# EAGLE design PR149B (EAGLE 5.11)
PID: 626
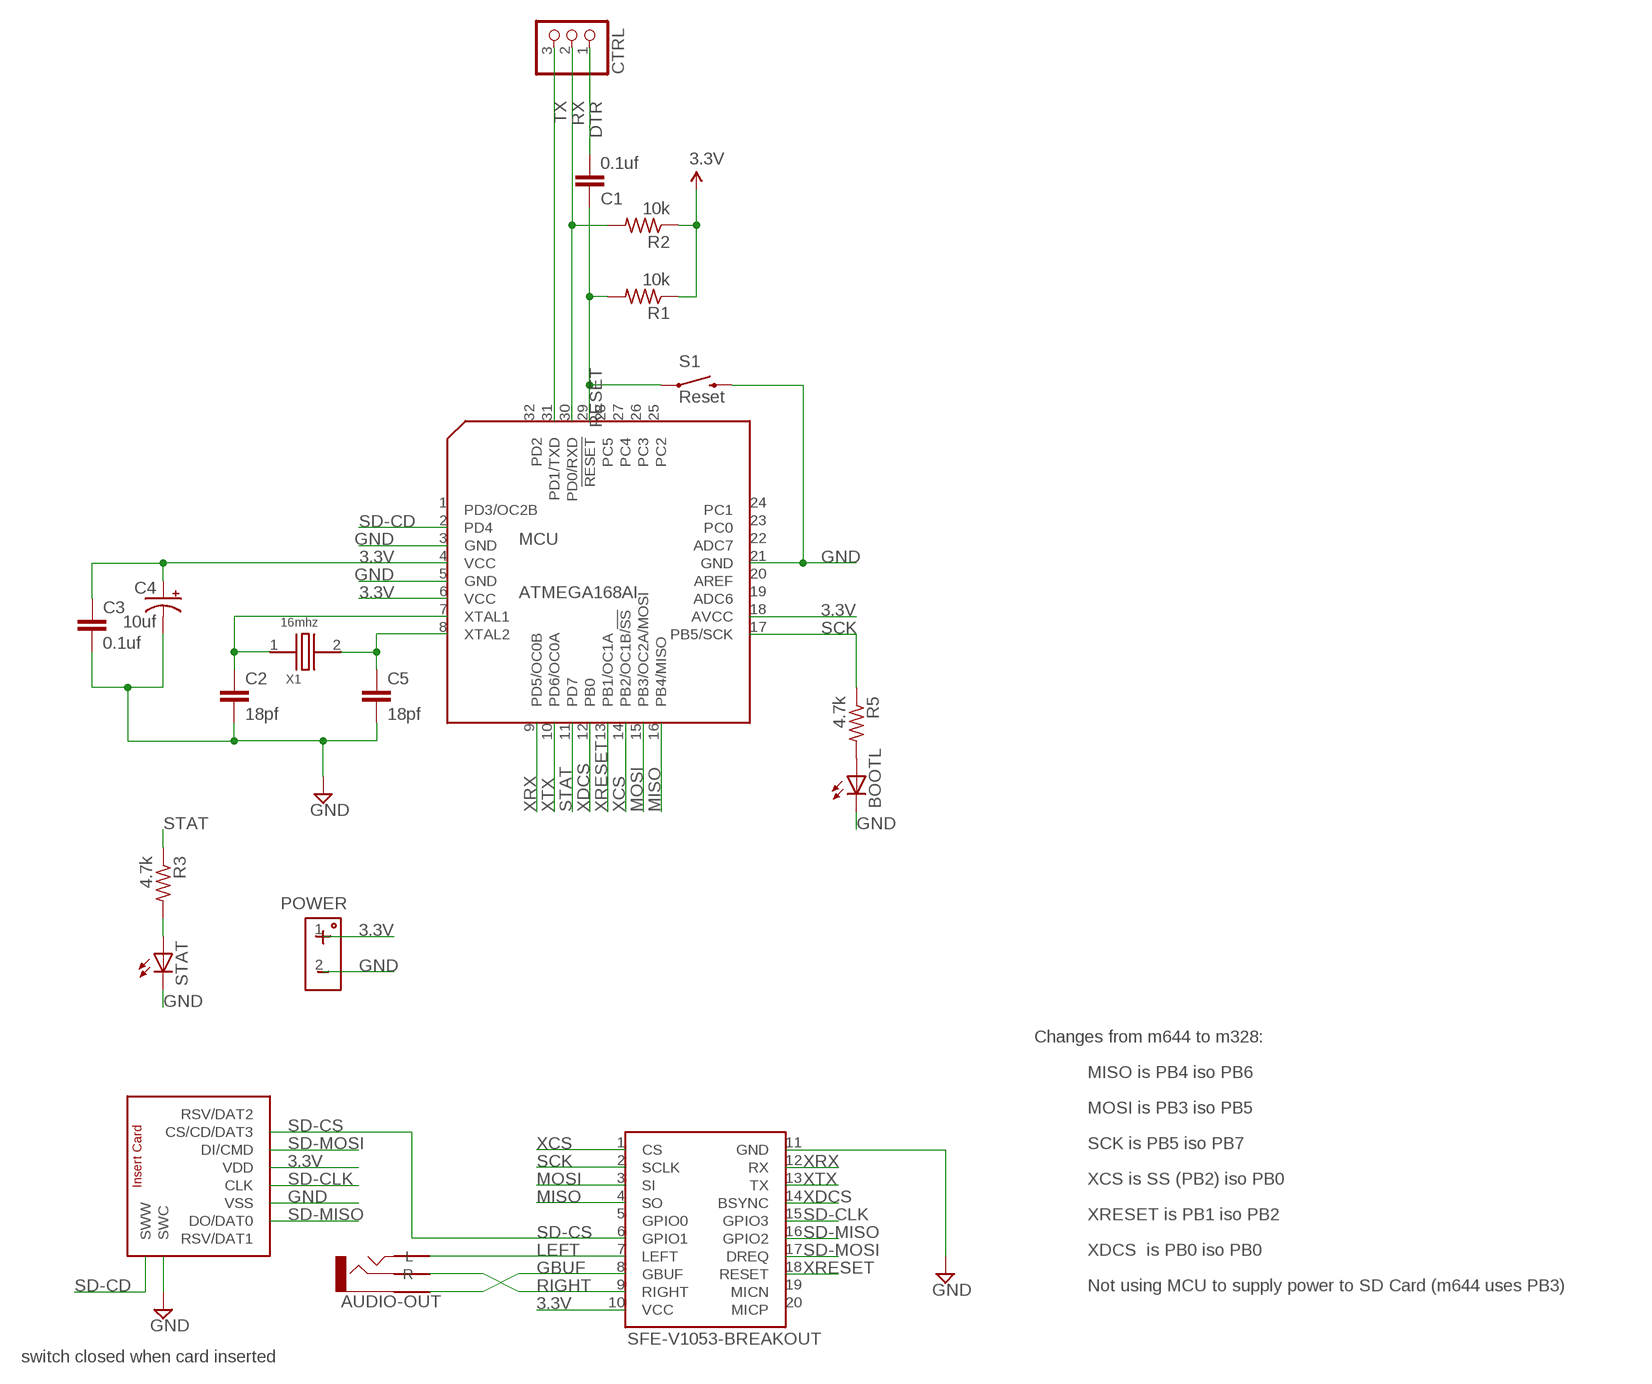
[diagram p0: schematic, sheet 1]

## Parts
AUDIO-OUT  AUDIO-JACK-STEREO-3PIN948  [AUDIO-JACK-STEREO-3PIN-948]
BOOTL  LEDCHIPLED_0805  [CHIPLED_0805]
C1  0.1uf  C-EUC1206  [C1206]
C2  18pf  C-EUC0805  [C0805]
C3  0.1uf  C-EUC1206  [C1206]
C4  10uf  CPOL-USB  [PANASONIC_B]
C5  18pf  C-EUC0805  [C0805]
CTRL  PINHD-1X3  [1X03]
MCU  ATMEGA168AI  [TQFP32-08]
POWER  HEADER-POWER  [HEADER-POWER]
R1  10k  R-US_M0805  [M0805]
R2  10k  R-US_R0805  [R0805]
R3  4.7k  R-US_R0805  [R0805]
R5  4.7k  R-US_R0805  [R0805]
S1  Reset  SWITCH-MOMENTARY-2-SMD-1101NE  [TACTILE-SWITCH-1101NE]
SFE-V1053-BREAKOUT  SFE-VS1053-BREAKOUT-DIL  [SFE-VS1053-BREAKOUT-DIL]
STAT  LEDCHIP-LED0805  [CHIP-LED0805]
U$1  SD-CARD-MICRO947  [SD-CARD-MICRO-947]
X1  16mhz  CRYSTAL-5X3.2MM  [CRYSTAL-5X3.2MM]

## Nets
3.3V: C3.1 C4.+ MCU.4(VCC) MCU.6(VCC) MCU.18(AVCC) POWER.1 R1.1 R2.1 SFE-V1053-BREAKOUT.10(VCC) U$1.VDD
DTR: C1.2 CTRL.1
GBUF: AUDIO-OUT.1(COM) SFE-V1053-BREAKOUT.8(GBUF)
GND: BOOTL.C C2.2 C3.2 C4.- C5.2 MCU.3(GND) MCU.5(GND) MCU.21(GND) POWER.2 S1.P$2 SFE-V1053-BREAKOUT.11(GND) STAT.C U$1.SWC U$1.VSS
LEFT: AUDIO-OUT.2(L) SFE-V1053-BREAKOUT.7(LEFT)
MISO: MCU.16(PB4/MISO) SFE-V1053-BREAKOUT.4(SO)
MOSI: MCU.15(PB3/OC2A/MOSI) SFE-V1053-BREAKOUT.3(SI)
N$1: R3.2 STAT.A
N$3: C2.1 MCU.7(XTAL1) X1.1
N$4: BOOTL.A R5.2
N$6: C5.1 MCU.8(XTAL2) X1.2
RESET: C1.1 MCU.29(!RESET) R1.2 S1.P$1
RIGHT: AUDIO-OUT.3(R) SFE-V1053-BREAKOUT.9(RIGHT)
RX: CTRL.2 MCU.30(PD0/RXD) R2.2
SCK: MCU.17(PB5/SCK) R5.1 SFE-V1053-BREAKOUT.2(SCLK)
SD-CD: MCU.2(PD4) U$1.SWW
SD-CLK: SFE-V1053-BREAKOUT.15(GPIO3) U$1.CLK
SD-CS: SFE-V1053-BREAKOUT.6(GPIO1) U$1.CD/DAT3(CS/CD/DAT3)
SD-MISO: SFE-V1053-BREAKOUT.16(GPIO2) U$1.DAT0(DO/DAT0)
SD-MOSI: SFE-V1053-BREAKOUT.17(DREQ) U$1.CMD(DI/CMD)
STAT: MCU.11(PD7) R3.1
TX: CTRL.3 MCU.31(PD1/TXD)
XCS: MCU.14(PB2/OC1B/!SS) SFE-V1053-BREAKOUT.1(CS)
XDCS: MCU.12(PB0) SFE-V1053-BREAKOUT.14(BSYNC)
XRESET: MCU.13(PB1/OC1A) SFE-V1053-BREAKOUT.18(RESET)
XRX: MCU.9(PD5/OC0B) SFE-V1053-BREAKOUT.12(RX)
XTX: MCU.10(PD6/OC0A) SFE-V1053-BREAKOUT.13(TX)
Unconnected: MCU.1(PD3/OC2B) MCU.19(ADC6) MCU.20(AREF) MCU.22(ADC7) MCU.23(PC0) MCU.24(PC1) MCU.25(PC2) MCU.26(PC3) MCU.27(PC4) MCU.28(PC5) MCU.32(PD2) SFE-V1053-BREAKOUT.5(GPIO0) SFE-V1053-BREAKOUT.19(MICN) SFE-V1053-BREAKOUT.20(MICP) U$1.DAT1(RSV/DAT1) U$1.DAT2(RSV/DAT2)

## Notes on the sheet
- Changes from m644 to m328:
- MISO is PB4 iso PB6
- MOSI is PB3 iso PB5
- SCK is PB5 iso PB7
- XCS is SS (PB2) iso PB0
- XRESET is PB1 iso PB2
- XDCS  is PB0 iso PB0
- Not using MCU to supply power to SD Card (m644 uses PB3)
- switch closed when card inserted

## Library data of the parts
AUDIO-OUT = trl:AUDIO-JACK-STEREO-3PIN
BOOTL STAT = led:LED: LED
C1-C3 C5 = rcl:C-EU: CAPACITOR, European symbol
C4 = rcl:CPOL-US: POLARIZED CAPACITOR, American symbol
CTRL = pinhead:PINHD-1X3: PIN HEADER
MCU = trl:ATMEGA168
POWER = trl:HEADER-POWER
R1-R3 R5 = resistor:R-US_: RESISTOR, American symbol
S1 = SparkFun2011-02-20:SWITCH-MOMENTARY-2
SFE-V1053-BREAKOUT = trl:SFE-VS1053-BREAKOUT-DIL
U$1 = trl:SD-CARD-MICRO
X1 = trl:CRYSTAL-5X3.2MM

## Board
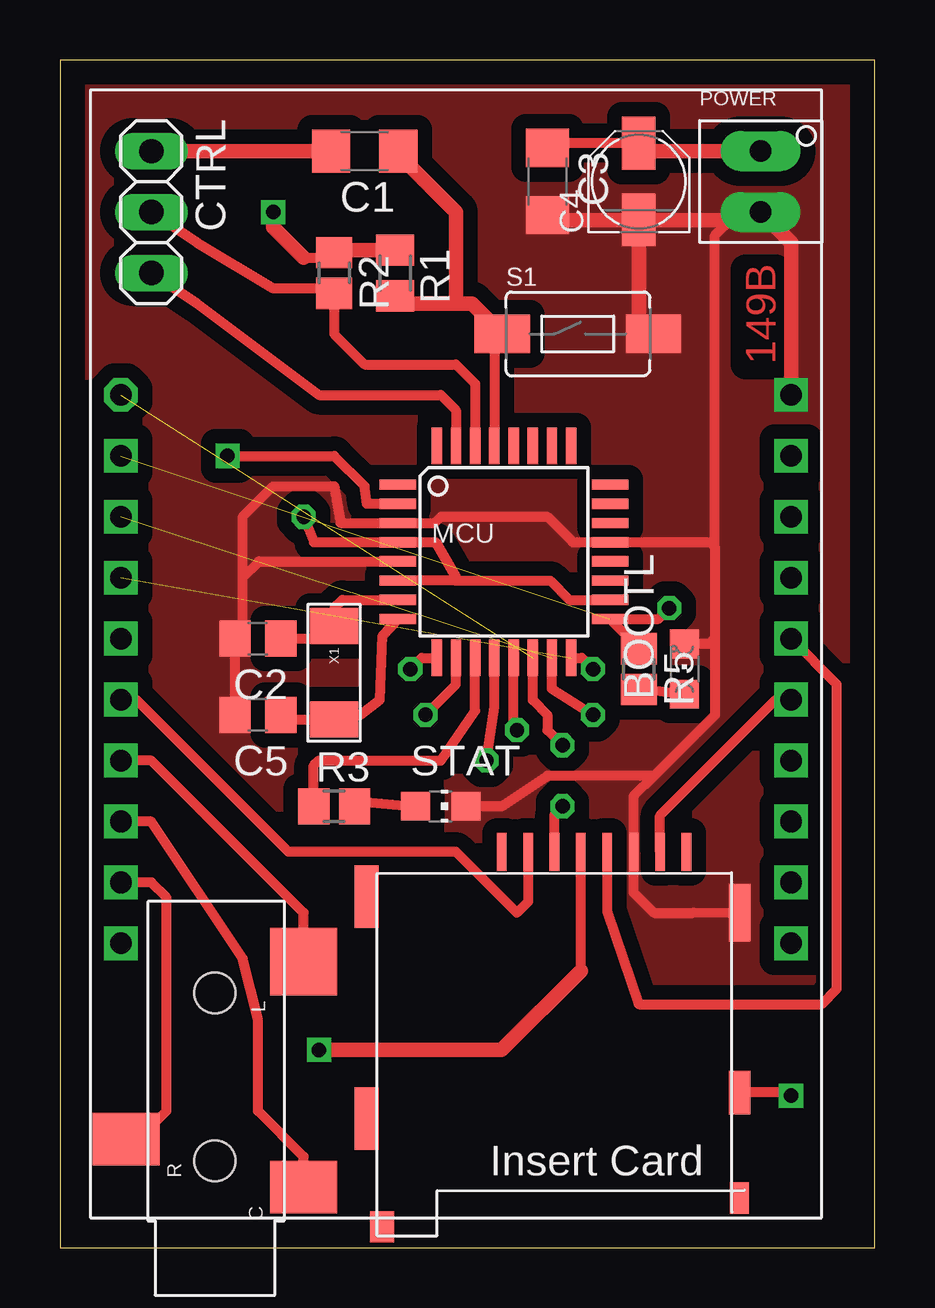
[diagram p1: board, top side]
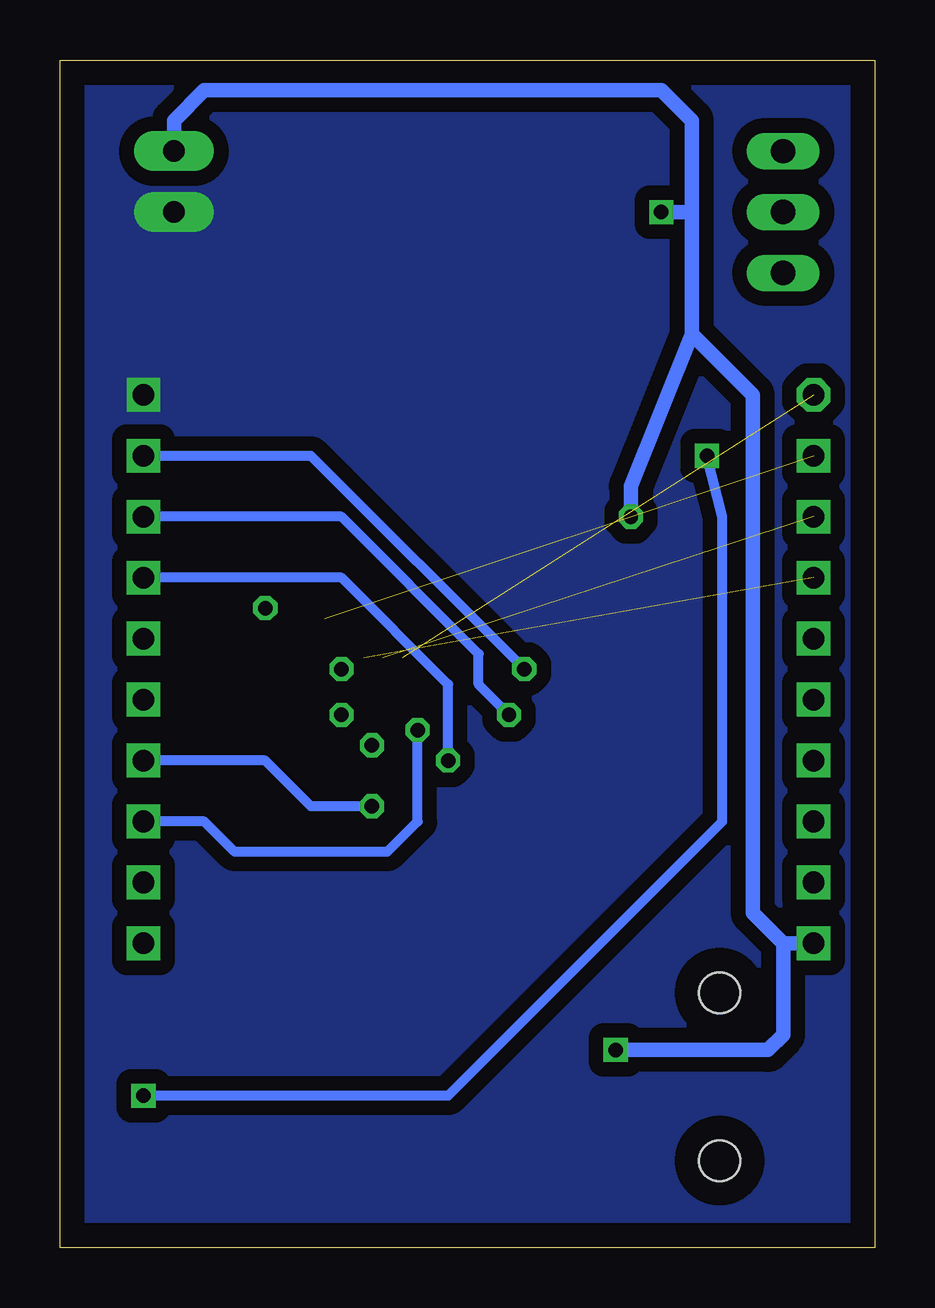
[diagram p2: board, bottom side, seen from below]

Size 33.96 x 49.52 mm. Coordinates in mm from the lower left corner, seen from the top.
Outline: 0,0 33.96,0 33.96,49.52 0,49.52 0,0
Copper layers (1*16): Top 0.035mm / dielectric 1.5mm / Bottom 0.035mm
Design rules "default": minimum track width 10mil, minimum drill 0.6mm, track to track 8mil, track to pad 8mil, pad to pad 8mil, via to via 8mil, smd to smd 8mil, copper to edge 40mil, drill to drill 8mil, minimum pad ring 10mil, minimum via ring 8mil, stop-mask expansion 4mil, vias tented up to drill 0mil, thermal gap 10mil

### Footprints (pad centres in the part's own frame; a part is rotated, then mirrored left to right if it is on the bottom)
AUDIO-JACK-STEREO-3PIN-948 = smd 2.2 x 2.8: 1 -3.81,-3.81; 3 -1.81,3.59 | smd 2.8 x 2.8: 2 5.59,-3.81 | hole 1.7: -2.71,-0.11; 4.29,-0.11
CHIPLED_0805 = smd 1.2 x 1.2: A 0,-1.05; C 0,1.05
C1206 = smd 1.6 x 1.8: 1 -1.4,0; 2 1.4,0
C0805 = smd 1.3 x 1.5: 1 -0.95,0; 2 0.95,0
PANASONIC_B = smd 2.2 x 1.4: + 1.6,0; - -1.6,0
1X03 = drill 1.016 long: 1 -2.54,0; 2 0,0; 3 2.54,0
TQFP32-08 = smd 1.524 x 0.432: 1 -3.69,2.61; 2 -3.69,1.81; 3 -3.69,1.01; 4 -3.69,0.21; 5 -3.69,-0.59; 6 -3.69,-1.39; 7 -3.69,-2.19; 8 -3.69,-2.99; 17 5.15,-2.99; 18 5.15,-2.19; 19 5.15,-1.39; 20 5.15,-0.59; 21 5.15,0.21; 22 5.15,1.01; 23 5.15,1.81; 24 5.15,2.61 | smd 0.432 x 1.524: 9 -2.07,-4.61; 10 -1.27,-4.61; 11 -0.47,-4.61; 12 0.33,-4.61; 13 1.13,-4.61; 14 1.93,-4.61; 15 2.73,-4.61; 16 3.53,-4.61; 25 3.53,4.23; 26 2.73,4.23; 27 1.93,4.23; 28 1.13,4.23; 29 0.33,4.23; 30 -0.47,4.23; 31 -1.27,4.23; 32 -2.07,4.23
HEADER-POWER = drill 0.9 pad 1.676 long: 1 0,1.27; 2 0,-1.27
M0805 = smd 1.3 x 1.6: 1 -0.95,0; 2 0.95,0
R0805 = smd 1.3 x 1.5: 1 -0.85,0; 2 0.85,0
TACTILE-SWITCH-1101NE = smd 2.3 x 1.6: P$1 -3.15,0; P$2 3.15,0
SFE-VS1053-BREAKOUT-DIL = drill 0.9 octagon: 1 -13.97,10.16 | drill 0.9 square: 2 -13.97,7.62; 3 -13.97,5.08; 4 -13.97,2.54; 5 -13.97,0; 6 -13.97,-2.54; 7 -13.97,-5.08; 8 -13.97,-7.62; 9 -13.97,-10.16; 10 -13.97,-12.7; 11 13.97,10.16; 12 13.97,7.62; 13 13.97,5.08; 14 13.97,2.54; 15 13.97,0; 16 13.97,-2.54; 17 13.97,-5.08; 18 13.97,-7.62; 19 13.97,-10.16; 20 13.97,-12.7
CHIP-LED0805 = smd 1.2 x 1.2: A 0,-1.05; C 0,1.05
SD-CARD-MICRO-947 = smd 0.4 x 1.6: CD/DAT3 -2.71,7.62; CLK 0.59,7.62; CMD -1.61,7.62; DAT0 2.79,7.62; DAT1 3.89,7.62; DAT2 -3.81,7.62; VDD -0.51,7.62; VSS 1.69,7.62 | smd 1 x 2.6: SH1 -9.45,5.75; SH2 -9.45,-3.5 | smd 1 x 1.3: SH3 -8.8,-8 | smd 0.8 x 1.3: SH4 6.1,-6.81 | smd 0.9 x 2.4: SWC 6.1,5.09 | smd 0.9 x 1.8: SWW 6.1,-2.41
CRYSTAL-5X3.2MM = smd 1.5 x 2: 1 -1.8,0; 2 2.1,0

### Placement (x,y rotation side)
AUDIO-OUT  6.35,6.35 90 top
BOOTL  26.04,24.13 0 top
C1  12.7,45.72 180 top
C2  8.26,25.4 180 top
C3  20.32,44.45 270 top
C4  24.13,44.45 90 top
C5  8.26,22.23 180 top
CTRL  3.81,43.18 270 top
MCU  17.78,29.21 0 top
POWER  29.21,44.45 0 top
R1  13.97,40.64 270 top
R2  11.43,40.64 270 top
R3  11.43,18.41 0 top
R5  24.13,24.13 270 top
S1  21.59,38.1 0 top
SFE-V1053-BREAKOUT  16.51,25.4 0 top
STAT  15.88,18.41 270 top
U$1  22.23,8.89 0 top
X1  11.43,24.13 270 top

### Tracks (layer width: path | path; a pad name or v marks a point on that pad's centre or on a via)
3.3V  (via drill 0.6)
  Top 0.406: R2.1 12.16,41.59 | 24.46,45.72 C4.+ 20.52,46.05 C3.1 | 10.16,41.27 11.21,41.27 | 16.51,27.82 MCU.6 | 16.51,27.82 20.44,27.82 21.24,27.02 MCU.18 | 16.51,27.82 16.51,27.94 15.66,29.42 MCU.4 10.59,29.42 v10.16,30.48 | 21.71,11.55 U$1.VDD
  Top 0.61: 12.16,41.59 R1.1 | v8.89,43.18 8.89,42.55 10.16,41.27 | 11.21,41.27 R2.1 | 21.71,11.55 18.41,8.26 v10.79,8.26 | POWER.1 24.46,45.72
  Bottom 0.61: POWER.1 29.21,46.99 27.94,48.26 8.89,48.26 7.62,46.99 7.62,43.18 | 7.62,38.1 7.62,43.18 | 7.62,38.1 5.08,35.56 5.08,13.97 3.81,12.7 | 3.81,12.7 SFE-V1053-BREAKOUT.10 | v10.79,8.26 4.45,8.26 3.81,8.89 3.81,12.7 | 7.62,43.18 v8.89,43.18 | 7.62,38.1 10.16,31.75 v10.16,30.48
DTR
  Top 0.61: CTRL.1 C1.2
GBUF
  Top 0.406: SFE-V1053-BREAKOUT.8 3.81,17.78 7.62,12.06 8.26,9.53 8.26,5.71 10.16,3.81 AUDIO-OUT.1
GND
  Top 0.406: 20.52,42.85 C3.2 | 28.88,42.85 POWER.2 | 24.13,38.71 S1.P$2 | C5.2 C2.2 7.62,25.71 7.62,27.94 | MCU.5 8.3,28.62 7.62,27.94 | U$1.SWC 26.41,13.97 24.77,13.97 23.91,14.82 U$1.VSS 23.91,18.84 24.77,19.68 | 7.62,27.94 7.62,30.48 8.89,31.75 11.43,31.75 11.69,30.22 MCU.3 15.62,30.22 15.88,30.48 20.32,30.48 21.38,29.42 MCU.21 27.09,29.42 27.3,29.21 | 24.77,19.68 27.3,22.23 27.3,25.4 | 27.3,29.21 27.3,25.4 | 27.3,29.21 27.3,42.22 27.94,42.85 | BOOTL.C 27.09,25.18 27.3,25.4 | STAT.C 18.41,18.41 20.32,19.68 24.77,19.68
  Top 0.61: C4.- 20.52,42.85 | C4.- 27.94,42.85 28.88,42.85 | C4.- 24.13,38.71 | SFE-V1053-BREAKOUT.11 30.48,41.91 POWER.2
  pour Top (isolate 0.61, no thermals): 0,49.53 33.66,49.53 33.66,0 0,0
  pour Bottom (isolate 0.61, no thermals): 0,49.53 33.66,49.53 33.66,0 0,0
LEFT
  Top 0.406: AUDIO-OUT.2 10.16,13.97 3.81,20.32 SFE-V1053-BREAKOUT.7
MISO  (via drill 0.6)  (1 unrouted)
  Top 0.406: MCU.16 21.75,24.6 v22.23,24.13
MOSI  (via drill 0.6)  (1 unrouted)
  Top 0.406: MCU.15 20.51,23.3 v22.23,22.23
N$1
  Top 0.406: STAT.A 12.27,18.64 R3.2
N$3
  Top 0.406: C2.1 10.9,25.4 X1.1 11.43,26.67 11.78,27.02 MCU.7
N$4
  Top 0.406: R5.2 24.57,23.28 BOOTL.A
N$6
  Top 0.406: MCU.8 13.46,25.52 13.34,22.86 12.51,22.23 X1.2 9.4,22.03 C5.1
RESET
  Top 0.406: MCU.29 18.11,37.77 S1.P$1
  Top 0.61: C1.1 14.1,45.59 16.51,43.18 16.51,39.37 | 16.51,39.37 17.17,39.37 S1.P$1 | 16.51,39.37 14.29,39.37 R1.2
RIGHT
  Top 0.406: SFE-V1053-BREAKOUT.9 3.81,15.24 4.45,14.61 4.45,5.71 3.81,5.08 3.3,5.08 AUDIO-OUT.3
RX
  Top 0.406: MCU.30 17.31,36.03 16.51,36.83 12.7,36.83 11.43,38.1 R2.2 11.21,40.01 8.89,40.01 5.71,41.91 CTRL.2
SCK  (via drill 0.6)  (1 unrouted)
  Top 0.406: R5.1 24.17,24.98 MCU.17 24.95,26.22 v25.4,26.67
SD-CD  (via drill 0.6)
  Top 0.406: MCU.2 12.79,31.02 12.7,31.75 11.43,33.02 v6.99,33.02 | U$1.SWW 30.35,6.48 v30.48,6.35
  Bottom 0.406: v30.48,6.35 17.78,6.35 6.35,17.78 6.35,30.48 v6.99,33.02
SD-CLK
  Top 0.406: SFE-V1053-BREAKOUT.15 32.38,23.5 32.38,10.79 31.75,10.16 24.13,10.16 22.82,14.02 U$1.CLK
SD-CS
  Top 0.406: U$1.CD/DAT3 19.52,14.44 19.05,13.97 16.51,16.51 9.53,16.51 3.17,22.86 SFE-V1053-BREAKOUT.6
SD-MISO
  Top 0.406: SFE-V1053-BREAKOUT.16 29.84,22.86 25.02,18.03 U$1.DAT0
SD-MOSI  (via drill 0.6)
  Top 0.406: U$1.CMD 20.61,18.07 v20.95,18.41
  Bottom 0.406: v20.95,18.41 23.5,18.41 25.4,20.32 SFE-V1053-BREAKOUT.17
STAT
  Top 0.406: R3.1 10.58,20.11 10.79,20.32 15.88,20.32 17.31,22.39 MCU.11
TX
  Top 0.406: MCU.31 16.51,34.92 15.88,35.56 10.79,35.56 5.71,39.37 CTRL.3
XCS  (via drill 0.6)  (1 unrouted)
  Top 0.406: MCU.14 19.71,22.84 20.32,22.23 20.32,21.59 v20.95,20.95
XDCS  (via drill 0.6)
  Top 0.406: MCU.12 18.11,22.55 v17.78,20.32
  Bottom 0.406: v17.78,20.32 17.78,23.5 22.23,27.94 SFE-V1053-BREAKOUT.14
XRESET  (via drill 0.6)
  Top 0.406: MCU.13 18.91,21.73 v19.05,21.59
  Bottom 0.406: v19.05,21.59 19.05,17.78 20.32,16.51 26.67,16.51 27.94,17.78 SFE-V1053-BREAKOUT.18
XRX  (via drill 0.6)
  Top 0.406: MCU.9 15.07,24.6 v14.61,24.13
  Bottom 0.406: v14.61,24.13 23.5,33.02 SFE-V1053-BREAKOUT.12
XTX  (via drill 0.6)
  Top 0.406: MCU.10 16.51,23.5 v15.24,22.23
  Bottom 0.406: v15.24,22.23 16.51,23.5 16.51,24.77 22.23,30.48 SFE-V1053-BREAKOUT.13

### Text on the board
Top: 149B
